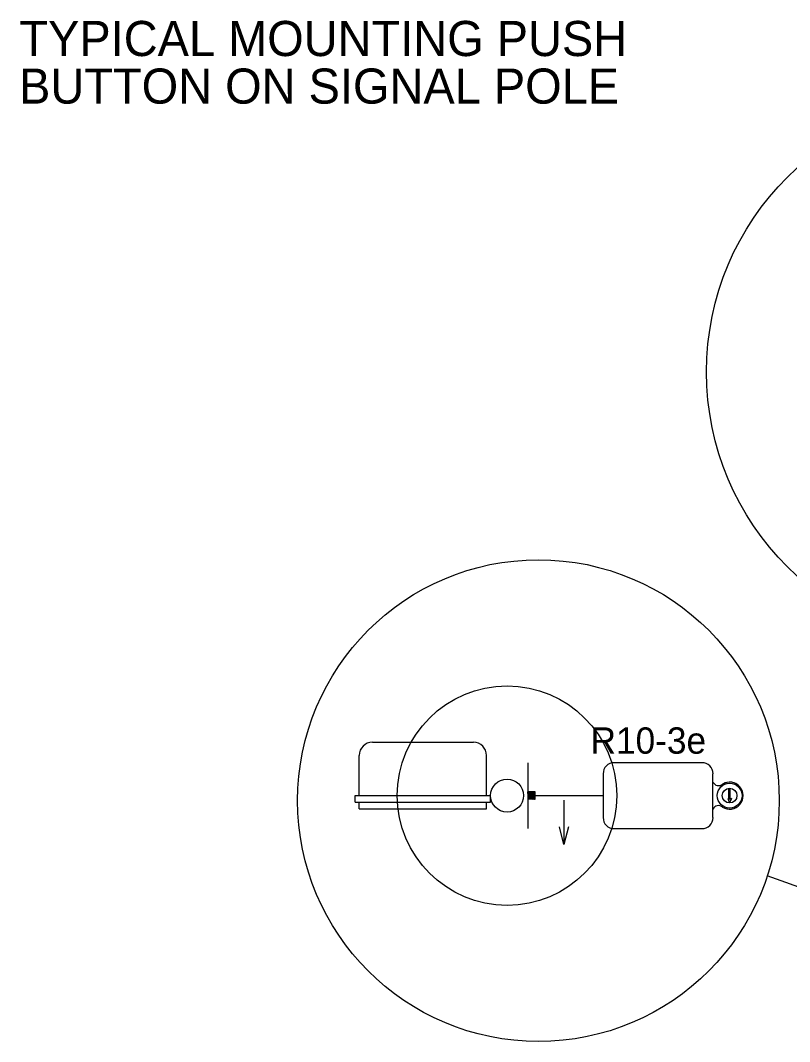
# Model space of a CAD drawing. Extents: x 1369885 to 1370886, y 379976 to 380616.
# Drawn here: x 1370614.6 to 1370746, y 380084.8 to 380259.3 of the extents above; entities that cross this region are included whole.
import ezdxf

# ---------------------------------------------------------------- set-up
doc = ezdxf.new("R2010")
doc.units = 0
doc.layers.add('R_Draft', color=7, linetype='Continuous')
doc.layers.add('T_Drafting', color=7, linetype='Continuous')

msp = doc.modelspace()

# ---------------------------------------------------------------- linework, layer by layer
at = {"layer": 'T_Drafting'}
for p, q in [((1370674.74, 380135.94), (1370691.99, 380135.94)), ((1370672.49, 380126.82), (1370672.49, 380133.69)), ((1370694.24, 380126.82), (1370694.24, 380133.69)), ((1370701.31, 380132.44), (1370701.31, 380121.19)), ((1370731.06, 380132.44), (1370716.04, 380132.44)), ((1370714.16, 380130.57), (1370714.16, 380123.07)), ((1370732.93, 380123.07), (1370732.93, 380130.57)), ((1370671.81, 380126.82), (1370694.93, 380126.82)), ((1370671.81, 380125.69), (1370671.81, 380126.82)), ((1370694.93, 380125.69), (1370694.93, 380126.82)), ((1370702.56, 380127.44), (1370701.31, 380127.44)), ((1370701.31, 380126.2), (1370702.55, 380127.44)), ((1370701.31, 380126.22), (1370702.53, 380127.44)), ((1370701.31, 380126.24), (1370702.51, 380127.44)), ((1370701.31, 380126.26), (1370702.49, 380127.44)), ((1370701.31, 380126.28), (1370702.47, 380127.44)), ((1370701.31, 380126.3), (1370702.45, 380127.44)), ((1370701.31, 380126.32), (1370702.43, 380127.44)), ((1370701.31, 380126.35), (1370702.4, 380127.44)), ((1370701.31, 380126.37), (1370702.38, 380127.44)), ((1370701.31, 380126.39), (1370702.36, 380127.44)), ((1370701.31, 380126.41), (1370702.34, 380127.44)), ((1370701.31, 380126.43), (1370702.32, 380127.44)), ((1370701.31, 380126.45), (1370702.3, 380127.44)), ((1370701.31, 380126.47), (1370702.28, 380127.44)), ((1370701.31, 380126.49), (1370702.26, 380127.44)), ((1370701.31, 380126.52), (1370702.23, 380127.44)), ((1370701.31, 380126.54), (1370702.21, 380127.44)), ((1370701.31, 380126.56), (1370702.19, 380127.44)), ((1370701.31, 380126.58), (1370702.17, 380127.44)), ((1370701.31, 380126.6), (1370702.15, 380127.44)), ((1370701.31, 380126.62), (1370702.13, 380127.44)), ((1370701.31, 380126.64), (1370702.11, 380127.44)), ((1370701.31, 380126.66), (1370702.09, 380127.44)), ((1370701.31, 380126.69), (1370702.06, 380127.44)), ((1370701.31, 380126.71), (1370702.04, 380127.44)), ((1370701.31, 380126.73), (1370702.02, 380127.44)), ((1370701.31, 380126.75), (1370702, 380127.44)), ((1370701.31, 380126.77), (1370701.98, 380127.44)), ((1370701.31, 380126.79), (1370701.96, 380127.44)), ((1370701.31, 380126.81), (1370701.94, 380127.44)), ((1370701.31, 380126.83), (1370701.92, 380127.44)), ((1370701.31, 380126.85), (1370701.89, 380127.44)), ((1370701.31, 380126.88), (1370701.87, 380127.44)), ((1370701.31, 380126.9), (1370701.85, 380127.44)), ((1370701.31, 380126.92), (1370701.83, 380127.44)), ((1370701.31, 380126.94), (1370701.81, 380127.44)), ((1370701.31, 380126.96), (1370701.79, 380127.44)), ((1370701.31, 380126.98), (1370701.77, 380127.44)), ((1370701.31, 380127), (1370701.75, 380127.44)), ((1370701.31, 380127.02), (1370701.73, 380127.44)), ((1370701.31, 380127.05), (1370701.7, 380127.44)), ((1370701.31, 380127.07), (1370701.68, 380127.44)), ((1370701.31, 380127.09), (1370701.66, 380127.44)), ((1370701.31, 380127.11), (1370701.64, 380127.44)), ((1370701.31, 380127.13), (1370701.62, 380127.44)), ((1370701.31, 380127.15), (1370701.6, 380127.44)), ((1370701.31, 380127.17), (1370701.58, 380127.44)), ((1370701.31, 380127.19), (1370701.56, 380127.44)), ((1370701.31, 380127.22), (1370701.53, 380127.44)), ((1370701.31, 380127.24), (1370701.51, 380127.44)), ((1370701.31, 380127.26), (1370701.49, 380127.44)), ((1370701.31, 380127.28), (1370701.47, 380127.44)), ((1370701.31, 380127.3), (1370701.45, 380127.44)), ((1370701.31, 380127.32), (1370701.43, 380127.44)), ((1370701.31, 380127.34), (1370701.41, 380127.44)), ((1370701.31, 380127.36), (1370701.39, 380127.44)), ((1370701.31, 380127.39), (1370701.36, 380127.44)), ((1370701.31, 380127.41), (1370701.34, 380127.44)), ((1370701.31, 380127.43), (1370701.32, 380127.44)), ((1370701.32, 380126.19), (1370702.56, 380127.43)), ((1370701.34, 380126.19), (1370702.56, 380127.4)), ((1370701.37, 380126.19), (1370702.56, 380127.38)), ((1370701.39, 380126.19), (1370702.56, 380127.36)), ((1370701.41, 380126.19), (1370702.56, 380127.34)), ((1370701.43, 380126.19), (1370702.56, 380127.32)), ((1370701.45, 380126.19), (1370702.56, 380127.3)), ((1370701.47, 380126.19), (1370702.56, 380127.28)), ((1370701.49, 380126.19), (1370702.56, 380127.26)), ((1370701.51, 380126.19), (1370702.56, 380127.24)), ((1370701.54, 380126.19), (1370702.56, 380127.21)), ((1370701.56, 380126.19), (1370702.56, 380127.19)), ((1370701.58, 380126.19), (1370702.56, 380127.17)), ((1370701.6, 380126.19), (1370702.56, 380127.15)), ((1370701.62, 380126.19), (1370702.56, 380127.13)), ((1370701.64, 380126.19), (1370702.56, 380127.11)), ((1370701.66, 380126.19), (1370702.56, 380127.09)), ((1370701.68, 380126.19), (1370702.56, 380127.07)), ((1370701.71, 380126.19), (1370702.56, 380127.04)), ((1370701.73, 380126.19), (1370702.56, 380127.02)), ((1370701.75, 380126.19), (1370702.56, 380127)), ((1370701.77, 380126.19), (1370702.56, 380126.98)), ((1370701.79, 380126.19), (1370702.56, 380126.96)), ((1370701.81, 380126.19), (1370702.56, 380126.94)), ((1370701.83, 380126.19), (1370702.56, 380126.92)), ((1370701.85, 380126.19), (1370702.56, 380126.9)), ((1370701.88, 380126.19), (1370702.56, 380126.87)), ((1370701.9, 380126.19), (1370702.56, 380126.85)), ((1370701.92, 380126.19), (1370702.56, 380126.83)), ((1370701.94, 380126.19), (1370702.56, 380126.81)), ((1370701.96, 380126.19), (1370702.56, 380126.79)), ((1370701.98, 380126.19), (1370702.56, 380126.77)), ((1370702, 380126.19), (1370702.56, 380126.75)), ((1370702.02, 380126.19), (1370702.56, 380126.73)), ((1370702.04, 380126.19), (1370702.56, 380126.7)), ((1370702.07, 380126.19), (1370702.56, 380126.68)), ((1370702.09, 380126.19), (1370702.56, 380126.66)), ((1370702.11, 380126.19), (1370702.56, 380126.64)), ((1370702.56, 380126.19), (1370702.56, 380127.44)), ((1370702.56, 380126.82), (1370714.16, 380126.82)), ((1370735.67, 380128.06), (1370735.9, 380128.06)), ((1370735.67, 380126.18), (1370735.67, 380128.06)), ((1370735.9, 380126.18), (1370735.9, 380128.06)), ((1370671.81, 380125.69), (1370694.93, 380125.69)), ((1370672.49, 380124.57), (1370672.49, 380125.69)), ((1370694.24, 380124.57), (1370694.24, 380125.69)), ((1370702.56, 380126.19), (1370701.31, 380126.19)), ((1370702.13, 380126.19), (1370702.56, 380126.62)), ((1370702.15, 380126.19), (1370702.56, 380126.6)), ((1370702.17, 380126.19), (1370702.56, 380126.58)), ((1370702.19, 380126.19), (1370702.56, 380126.56)), ((1370702.21, 380126.19), (1370702.56, 380126.54)), ((1370702.24, 380126.19), (1370702.56, 380126.51)), ((1370702.26, 380126.19), (1370702.56, 380126.49)), ((1370702.28, 380126.19), (1370702.56, 380126.47)), ((1370702.3, 380126.19), (1370702.56, 380126.45)), ((1370702.32, 380126.19), (1370702.56, 380126.43)), ((1370702.34, 380126.19), (1370702.56, 380126.41)), ((1370702.36, 380126.19), (1370702.56, 380126.39)), ((1370702.38, 380126.19), (1370702.56, 380126.37)), ((1370702.41, 380126.19), (1370702.56, 380126.34)), ((1370702.43, 380126.19), (1370702.56, 380126.32)), ((1370702.45, 380126.19), (1370702.56, 380126.3)), ((1370702.47, 380126.19), (1370702.56, 380126.28)), ((1370702.49, 380126.19), (1370702.56, 380126.26)), ((1370702.51, 380126.19), (1370702.56, 380126.24)), ((1370702.53, 380126.19), (1370702.56, 380126.22)), ((1370702.55, 380126.19), (1370702.56, 380126.2)), ((1370707.47, 380126.02), (1370707.47, 380118.47)), ((1370735.48, 380126.33), (1370735.78, 380125.57)), ((1370735.67, 380126.18), (1370735.48, 380126.33)), ((1370736.08, 380126.33), (1370735.78, 380125.57)), ((1370736.08, 380126.33), (1370735.9, 380126.18)), ((1370672.49, 380124.57), (1370694.24, 380124.57)), ((1370716.04, 380121.19), (1370731.06, 380121.19)), ((1370763.17, 380105.63), (1370742.21, 380113.09))]:
    msp.add_line(p, q, dxfattribs=at)
msp.add_lwpolyline([(1370708.22, 380121.47), (1370707.47, 380118.47), (1370706.72, 380121.47)], dxfattribs=at)
for centre, radius in [((1370778.86, 380199.21), 47.03), ((1370703.11, 380125.96), 41.16), ((1370697.74, 380126.82), 18.75), ((1370697.74, 380126.82), 2.81), ((1370735.78, 380126.82), 2.12), ((1370735.78, 380126.82), 1.25)]:
    msp.add_circle(centre, radius, dxfattribs=at)
for centre, radius, start, end in [((1370674.74, 380133.69), 2.25, 90, 180), ((1370691.99, 380133.69), 2.25, 360, 90), ((1370716.04, 380130.57), 1.88, 90, 180), ((1370731.06, 380130.57), 1.88, 0, 90), ((1370733.88, 380129.58), 1.05, 205.1956, 311.8028), ((1370735.78, 380126.82), 2.31, 238.7402, 121.2598), ((1370735.78, 380126.82), 2.31, 42.5066, 121.2598), ((1370733.88, 380124.06), 1.05, 48.1972, 154.8044), ((1370735.78, 380126.82), 2.31, 238.7402, 317.4934), ((1370716.04, 380123.07), 1.88, 180, 270), ((1370731.06, 380123.07), 1.88, 270, 0)]:
    msp.add_arc(centre, radius, start, end, dxfattribs=at)

# ---------------------------------------------------------------- texts
at = {"layer": 'R_Draft'}
for s, p in [('TYPICAL MOUNTING PUSH ', (1370614.4, 380253.19)), ('BUTTON ON SIGNAL POLE ', (1370614.35, 380245.06))]:
    msp.add_text(s, height=6, dxfattribs=at).set_placement(p)
at = {"layer": 'T_Drafting'}
msp.add_text('R10-3e', height=4.5, dxfattribs=at).set_placement((1370712.02, 380133.98))

doc.saveas('drawing.dxf')
